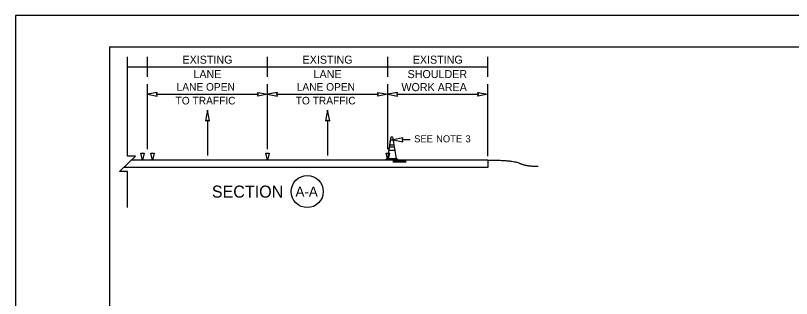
# Model space of a CAD drawing. Extents: x 99999.1 to 100096.1, y 99995 to 100010.7.
# Drawn here: x 99999.06 to 100006.81, y 100007.86 to 100010.69 of the extents above; entities that cross this region are included whole.
import ezdxf

# ---------------------------------------------------------------- set-up
doc = ezdxf.new("R2010")
doc.units = 0
for name, color, linetype in [('SH_GI_PlotLimits', 7, 'Continuous'), ('SH_GI_SheetBorder', 7, 'Continuous'), ('SH_TI_WZSectionCut', 7, 'Continuous'), ('TR_WZ_ArrowLeftStrRightTurn', 7, 'Continuous'), ('TR_WZ_TrafficConeElev', 7, 'Continuous'), ('TR_WZ_WorkZoneDetails', 7, 'Continuous'), ('TR_WZ_WorkZoneTextCurrent', 7, 'Continuous')]:
    doc.layers.add(name, color=color, linetype=linetype)

msp = doc.modelspace()

# ---------------------------------------------------------------- linework, layer by layer
at = {"layer": 'SH_GI_PlotLimits'}
msp.add_lwpolyline([(99999.0625, 99999.6875), (100016.0625, 99999.6875), (100016.0625, 100010.6875), (99999.0625, 100010.6875)], close=True, dxfattribs=at)
at = {"layer": 'SH_GI_SheetBorder'}
for q in [(100000, 100000), (100015.75, 100010.375)]:
    msp.add_line((100000, 100010.375), q, dxfattribs=at)
at = {"layer": 'SH_TI_WZSectionCut'}
for p, q in [((100000.38, 100010.075), (100000.38, 100010.275)), ((100001.58, 100010.075), (100001.58, 100010.275)), ((100002.78, 100010.075), (100002.78, 100010.275)), ((100003.78, 100010.075), (100003.78, 100010.275)), ((100000.18, 100010.175), (100000.38, 100010.175)), ((100000.38, 100010.175), (100001.58, 100010.175)), ((100001.58, 100010.175), (100002.78, 100010.175)), ((100002.78, 100010.175), (100003.78, 100010.175)), ((100000.38, 100009.3547), (100000.38, 100010.001)), ((100001.58, 100009.3547), (100001.58, 100010.001)), ((100002.78, 100009.3547), (100002.78, 100010.001)), ((100003.78, 100009.2849), (100003.78, 100010.001)), ((100000.4738, 100009.901), (100001.4863, 100009.901)), ((100001.6738, 100009.901), (100002.6863, 100009.901)), ((100002.8738, 100009.901), (100003.6863, 100009.901)), ((100003.78, 100009.2449), (100000.2188, 100009.2449)), ((100002.963, 100009.2393), (100002.83, 100009.2393)), ((100002.963, 100009.2337), (100002.83, 100009.2337)), ((100002.963, 100009.228), (100002.83, 100009.228)), ((100002.963, 100009.2228), (100002.83, 100009.2228)), ((100003.78, 100009.2449), (100003.78, 100009.1699)), ((100003.78, 100009.1699), (100000.1413, 100009.1699))]:
    msp.add_line(p, q, dxfattribs=at)
for points in [[(100000.38, 100009.901), (100000.4783, 100009.8817), (100000.4738, 100009.901), (100000.4783, 100009.9203)], [(100001.58, 100009.901), (100001.4817, 100009.8817), (100001.4863, 100009.901), (100001.4817, 100009.9203)], [(100001.58, 100009.901), (100001.6783, 100009.8817), (100001.6738, 100009.901), (100001.6783, 100009.9203)], [(100002.78, 100009.901), (100002.6817, 100009.8817), (100002.6863, 100009.901), (100002.6817, 100009.9203)], [(100002.78, 100009.901), (100002.8783, 100009.8817), (100002.8738, 100009.901), (100002.8783, 100009.9203)], [(100003.78, 100009.901), (100003.6817, 100009.8817), (100003.6863, 100009.901), (100003.6817, 100009.9203)], [(100000.3133, 100009.3147), (100000.3467, 100009.3147), (100000.33, 100009.2449)], [(100000.4133, 100009.3147), (100000.4467, 100009.3147), (100000.43, 100009.2449)], [(100001.5634, 100009.3147), (100001.5967, 100009.3147), (100001.5801, 100009.2449)], [(100002.7634, 100009.3147), (100002.7967, 100009.3147), (100002.7801, 100009.2449)]]:
    msp.add_lwpolyline(points, close=True, dxfattribs=at)
msp.add_circle((100001.9766, 100008.93), 0.16, dxfattribs=at)
msp.add_open_spline([(100003.78, 100009.2449), (100004.0312, 100009.2451), (100004.1567, 100009.183), (100004.2822, 100009.1831)], degree=2, dxfattribs=at)
at = {"layer": 'TR_WZ_ArrowLeftStrRightTurn'}
for p, q in [((100000.98, 100009.6418), (100000.98, 100009.292)), ((100002.18, 100009.6418), (100002.18, 100009.292))]:
    msp.add_line(p, q, dxfattribs=at)
for points in [[(100000.98, 100009.742), (100000.9594, 100009.6369), (100000.98, 100009.6418), (100001.0006, 100009.6369)], [(100002.18, 100009.742), (100002.1594, 100009.6369), (100002.18, 100009.6418), (100002.2006, 100009.6369)]]:
    msp.add_lwpolyline(points, close=True, dxfattribs=at)
at = {"layer": 'TR_WZ_TrafficConeElev'}
for p, q in [((100002.8008, 100009.3929), (100002.8091, 100009.4471)), ((100002.8091, 100009.4471), (100002.8343, 100009.4471)), ((100002.8343, 100009.4471), (100002.8426, 100009.3929)), ((100002.7925, 100009.3388), (100002.7982, 100009.3763)), ((100002.8509, 100009.3388), (100002.7925, 100009.3388)), ((100002.7982, 100009.3763), (100002.8452, 100009.3763)), ((100002.8426, 100009.3929), (100002.8008, 100009.3929)), ((100002.8452, 100009.3763), (100002.8509, 100009.3388)), ((100002.7639, 100009.2533), (100002.7681, 100009.2575)), ((100002.7639, 100009.245), (100002.7639, 100009.2533)), ((100002.8634, 100009.2575), (100002.8753, 100009.2575)), ((100002.8753, 100009.2575), (100002.8795, 100009.2533)), ((100002.8795, 100009.2533), (100002.8795, 100009.245)), ((100002.8795, 100009.245), (100002.7639, 100009.245))]:
    msp.add_line(p, q, dxfattribs=at)
msp.add_lwpolyline([(100002.8634, 100009.2575), (100002.78, 100009.2575), (100002.8139, 100009.4783), (100002.8295, 100009.4783)], close=True, dxfattribs=at)
msp.add_lwpolyline([(100002.8634, 100009.2575), (100002.78, 100009.2575), (100002.8139, 100009.4783), (100002.8295, 100009.4783)], close=True, dxfattribs=at)
msp.add_lwpolyline([(100002.7681, 100009.2575), (100002.78, 100009.2575), (100002.8634, 100009.2575)], dxfattribs=at)
at = {"layer": 'TR_WZ_WorkZoneDetails'}
msp.add_line((100003.0043, 100009.4471), (100002.9281, 100009.4471), dxfattribs=at)
msp.add_lwpolyline([(100000.18, 100008.7701), (100000.18, 100009.13), (100000.1, 100009.13), (100000.2601, 100009.2849), (100000.18, 100009.2849), (100000.18, 100010.275)], dxfattribs=at)
msp.add_lwpolyline([(100002.8343, 100009.4471), (100002.9326, 100009.4279), (100002.928, 100009.4472), (100002.9326, 100009.4664)], close=True, dxfattribs=at)

# ---------------------------------------------------------------- texts
at = {"layer": 'SH_TI_WZSectionCut'}
for s, height, p in [('EXISTING', 0.08, (100000.7302, 100010.207)), ('EXISTING', 0.08, (100001.9302, 100010.207)), ('EXISTING', 0.08, (100003.0302, 100010.207)), ('LANE', 0.08, (100000.8396, 100010.063)), ('LANE', 0.08, (100002.0396, 100010.063)), ('SHOULDER', 0.08, (100002.9783, 100010.063)), ('SECTION', 0.12, (100001.0235, 100008.87)), ('A-A', 0.1, (100001.8587, 100008.88))]:
    msp.add_text(s, height=height, rotation=360, dxfattribs=at).set_placement(p)
for s, height, p in [('LANE OPEN', 0.076, (100000.6714, 100009.937)), ('LANE OPEN', 0.076, (100001.8714, 100009.937)), ('WORK AREA', 0.08, (100002.9171, 100009.933)), ('TO TRAFFIC', 0.076, (100000.6613, 100009.8002)), ('TO TRAFFIC', 0.076, (100001.8613, 100009.8002))]:
    msp.add_text(s, height=height, dxfattribs=at).set_placement(p)
at = {"layer": 'TR_WZ_WorkZoneTextCurrent'}
for s, p in [('SEE', (100003.0443, 100009.4221)), ('NOTE', (100003.2635, 100009.4221)), ('3', (100003.5567, 100009.4221))]:
    msp.add_text(s, height=0.07, dxfattribs=at).set_placement(p)

doc.saveas('drawing.dxf')
